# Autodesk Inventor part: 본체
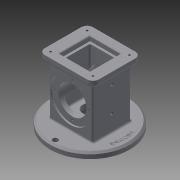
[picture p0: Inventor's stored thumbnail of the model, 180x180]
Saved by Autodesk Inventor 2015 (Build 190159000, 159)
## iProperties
Created: 2019-08
Part Number: 본체
Material: 일반
Document SubType Name: Modeling
Designer: now
Density: 1 g/cm^3
Appearance: 기본값
Author: now
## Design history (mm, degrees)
sketch "스케치1"
  geometry: C1 r 67.5 at (0, 0); 1 further point
  constraints: 1 centre point, 1 coincident
  dimensions: "d0" = 135 diameter of C1
extrude "돌출1" new body sketch "스케치1" distance "d1" = 10; taper "d2" = 0 deg
sketch "스케치2"
  geometry: L1 (-37, -33)-(37, -33); L2 (37, -33)-(37, 33); L3 (37, 33)-(-37, 33); L4 (-37, 33)-(-37, -33); L5 (-37, -33)-(37, 33); L6 (37, -33)-(-37, 33); C1 r 67.5 at (0, 0) reference
  constraints: 12 end point, 2 midpoint, 2 parallel, 1 horizontal, 1 perpendicular
  dimensions: "d3" = 74 distance of L2.end L3.end; "d4" = 66 distance of L1.end L2.end
extrude "돌출2" join sketch "스케치2" distance "d5" = 88; taper "d6" = 0 deg
sketch "스케치3"
  geometry: L1 (-46, -41)-(46, -41); L2 (46, -41)-(46, 41); L3 (46, 41)-(-46, 41); L4 (-46, 41)-(-46, -41); L5 (-46, -41)-(46, 41); L6 (46, -41)-(-46, 41); 1 further point
  constraints: 12 end point, 2 midpoint, 2 parallel, 1 horizontal, 1 perpendicular
  dimensions: "d7" = 92 distance of L2.end L3.end; "d8" = 82 distance of L1.end L2.end
extrude "돌출3" join sketch "스케치3" distance "d9" = 10; taper "d10" = 0 deg
chamfer "모따기1" distance "d11" = 3; stored, may be unused: second distance "d12" = 2, angle "d13" = 45 deg
fillet "모깎기1" dims "d14" = 10
sketch "스케치4"
  geometry: C1 r 67.5 at (0, 0) reference
hole "구멍1" sketch "스케치4" at (0, 0) diameter "d15" = 25; stored, may be unused: countersink angle "d19" = 90 deg, drill point angle "d21" = 0 deg; dims "d16" = 6, "d17" = 50, "d18" = 18, "d20" = 26
sketch "스케치5"
  geometry: L1 (-26, -26)-(26, -26); L2 (26, -26)-(26, 26); L3 (26, 26)-(-26, 26); L4 (-26, 26)-(-26, -26); L5 (-26, -26)-(26, 26); L6 (26, -26)-(-26, 26); 1 further point
  constraints: 12 end point, 2 midpoint, 2 parallel, 1 horizontal, 1 perpendicular
  dimensions: "d22" = 52 distance of L2.end L3.end; "d23" = 52 distance of L1.end L2.end
extrude "돌출4" cut sketch "스케치5" distance "d24" = 8; taper "d25" = 0 deg
sketch "스케치6"
  geometry: L1 (-22, -22)-(22, -22); L2 (22, -22)-(22, 22); L3 (22, 22)-(-22, 22); L4 (-22, 22)-(-22, -22); L5 (-22, -22)-(22, 22); L6 (22, -22)-(-22, 22); 1 further point
  constraints: 12 end point, 2 midpoint, 2 parallel, 1 horizontal, 1 perpendicular
  dimensions: "d26" = 44 distance of L2.end L3.end; "d27" = 44 distance of L3.end L1.start
extrude "돌출5" cut sketch "스케치6" distance "d28" = 74; taper "d29" = 0 deg
fillet "모깎기2" dims "d30" = 3
sketch "스케치8"
  geometry: L1 (-30.5, -10)-(104.5, -10) reference; 3 further points
  constraints: 1 midpoint, 1 vertical alignment
  dimensions: "d39" = 54 distance from line of L1 point (37, 44)
hole "구멍3" sketch "스케치8" at (37, 44) diameter "d40" = 70; stored, may be unused: countersink angle "d44" = 90 deg, drill point angle "d46" = 0 deg; dims "d41" = 6, "d42" = 50, "d43" = 18, "d45" = 3
fillet "모깎기3" dims "d54" = 3
fillet "모깎기4" dims "d55" = 3
sketch "스케치9"
  geometry: C1 r 35 at (0, 0) reference; 1 further point
hole "구멍4" sketch "스케치9" at (0, 0) diameter "d47" = 48; stored, may be unused: countersink angle "d51" = 90 deg, drill point angle "d53" = 0 deg; dims "d48" = 6, "d49" = 50, "d50" = 18, "d52" = 3
sketch "스케치10"
  geometry: C1 r 24 at (0, 0) reference; 2 further points
  constraints: 1 vertical alignment
  dimensions: "d56" = 29 distance of point (0, 29) C1.centre
hole "구멍5" sketch "스케치10" at (0, 29) diameter "d57" = 3.242; stored, may be unused: countersink angle "d61" = 90 deg, drill point angle "d63" = 118 deg; dims "d58" = 4, "d59" = 50, "d60" = 18, "d62" = 6
sketch "스케치11"
  geometry: A1 r 10 centre (36, 31) between (46, 31) and (36, 41) reference; A2 r 10 centre (-36, 31) between (-36, 41) and (-46, 31) reference; A3 r 10 centre (-36, -31) between (-46, -31) and (-36, -41) reference; A4 r 10 centre (36, -31) between (36, -41) and (46, -31) reference; 1 further point
hole "구멍6" sketch "스케치11" at (-36, 31), (36, 31), (-36, -31), (36, -31) diameter "d67" = 3.242; stored, may be unused: countersink angle "d71" = 90 deg, drill point angle "d73" = 118 deg; dims "d68" = 4, "d69" = 50, "d70" = 18, "d72" = 6
sketch "스케치13"
  geometry: C1 r 64.5 at (0, 0) reference; A1 r 59 centre (0, 0) between (0, 59) and (-59, 0)
  constraints: 2 point on circle, 1 centre point, 1 coincident, 1 horizontal alignment, 1 vertical alignment
  dimensions: "d74" = 118 diameter of A1
hole "구멍7" sketch "스케치13" at (0, 59), (-59, 0) diameter "d75" = 9; stored, may be unused: countersink angle "d79" = 90 deg, drill point angle "d81" = 0 deg; dims "d76" = 4, "d77" = 50, "d78" = 18, "d80" = 6
fillet "모깎기5" dims "d82" = 3
fillet "모깎기6" dims "d83" = 3
sketch "스케치14"
  geometry: C1 r 64.5 at (0, 0) reference; C2 r 59 at (0, 0)
  constraints: 1 centre point, 1 coincident, 1 other
  dimensions: "d84" = 118 diameter of C2
feature "엠보싱1" sketch "스케치14" dims "d1" = 10, "d9" = 10, "d85" = 0.5, "d86" = 0
fillet "모깎기7" dims "d87" = 3
sketch "스케치15"
  geometry: L1 (13, -37.5)-(13, 97.5) reference; 4 further points
  constraints: 2 horizontal alignment, 1 midpoint
  dimensions: "d88" = 37 distance from line of point (-24, 30) L1; "d89" = 43 distance of point (-67, 30) point (-24, 30)
hole "구멍8" sketch "스케치15" at (-67, 30), (-24, 30) diameter "d90" = 4.917; stored, may be unused: countersink angle "d94" = 90 deg, drill point angle "d96" = 0 deg; dims "d91" = 12, "d92" = 50, "d93" = 18, "d95" = 30
chamfer "모따기2" distance "d97" = 1; stored, may be unused: second distance "d98" = 2, angle "d99" = 45 deg
node "솔리드1"
mirror "대칭1"
pattern_circular "원형 패턴1" dims angle "d65" = 360 deg
mirror "대칭2"
mirror "대칭3"
